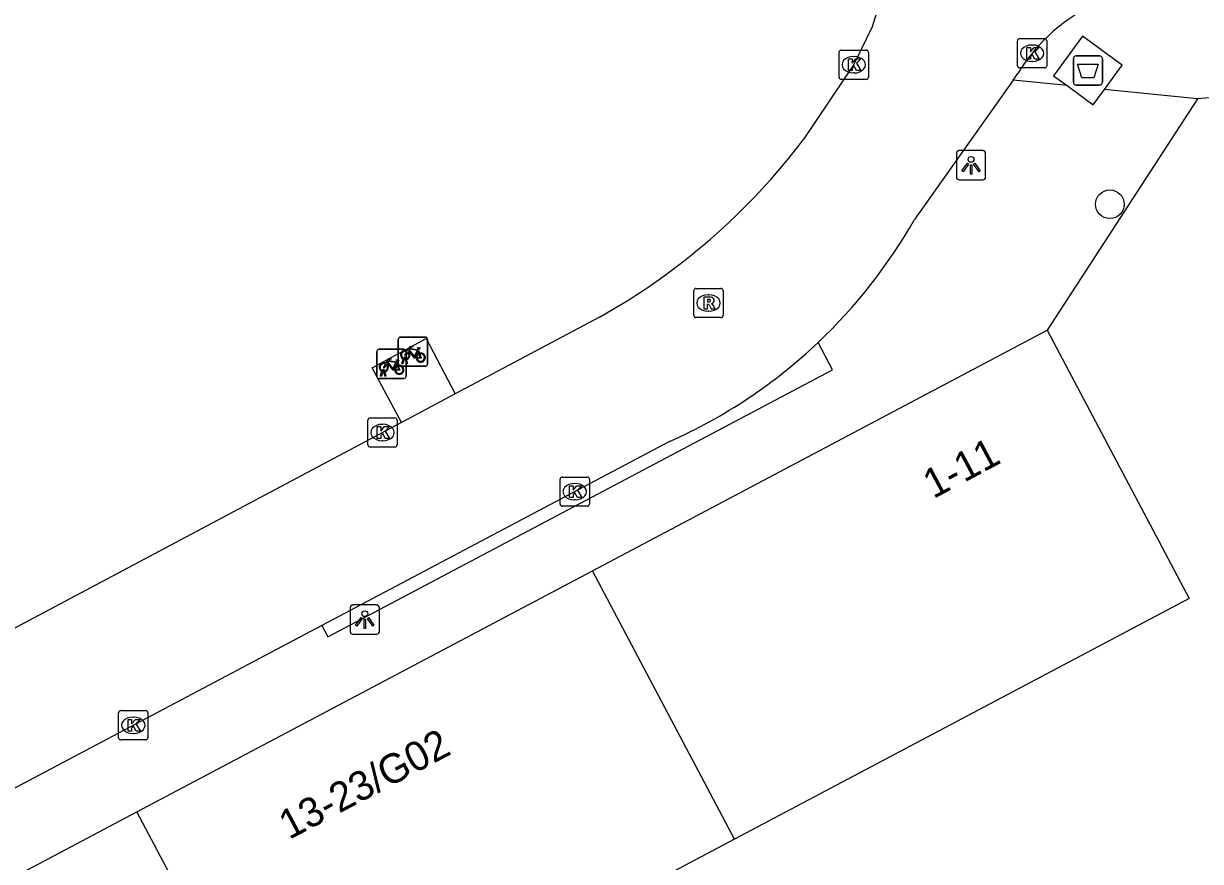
# Model space of a CAD drawing. Extents: x 159675 to 160530, y 382179 to 382901.
# Drawn here: x 160043.25 to 160083.44, y 382293.36 to 382321.97 of the extents above; entities that cross this region are included whole.
import ezdxf

# ---------------------------------------------------------------- set-up
doc = ezdxf.new("R2010")
doc.units = 0
for name, color, linetype in [('IMGEO_Afval_apart_plaats', 7, 'Continuous'), ('IMGEO_Boom', 7, 'Continuous'), ('IMGEO_Fietsenrek', 7, 'Continuous'), ('IMGEO_Groenvoorziening', 7, 'Continuous'), ('IMGEO_Kolk', 7, 'Continuous'), ('IMGEO_Lichtpunt', 7, 'Continuous'), ('IMGEO_Pand', 7, 'Continuous'), ('IMGEO_Pand_nummerreeks', 7, 'Continuous'), ('IMGEO_Rijbaan_lokaal_open', 7, 'Continuous'), ('IMGEO_Rioolput', 7, 'Continuous'), ('IMGEO_Voetpad_gesloten', 7, 'Continuous'), ('IMGEO_Voetpad_open', 7, 'Continuous')]:
    doc.layers.add(name, color=color, linetype=linetype)

msp = doc.modelspace()

# ---------------------------------------------------------------- linework, layer by layer
at = {"layer": 'IMGEO_Afval_apart_plaats'}
for p, q in [((160079.198, 382320.869), (160079.988, 382320.869)), ((160079.988, 382320.869), (160079.198, 382320.869)), ((160079.098, 382319.969), (160079.098, 382320.769)), ((160079.098, 382320.769), (160079.098, 382319.969)), ((160080.088, 382320.769), (160080.088, 382319.969)), ((160080.088, 382319.969), (160080.088, 382320.769)), ((160079.988, 382319.869), (160079.198, 382319.869)), ((160079.198, 382319.869), (160079.988, 382319.869))]:
    msp.add_line(p, q, dxfattribs=at)
msp.add_lwpolyline([(160079.241, 382320.583), (160079.945, 382320.583), (160079.796, 382320.113), (160079.39, 382320.113), (160079.241, 382320.583)], dxfattribs=at)
for centre, start, end in [((160079.198, 382320.769), 90, 180), ((160079.198, 382320.769), 90, 180), ((160079.988, 382320.769), 0, 90), ((160079.988, 382320.769), 360, 90), ((160079.198, 382319.969), 180, 270), ((160079.198, 382319.969), 180, 270), ((160079.988, 382319.969), 270, 0), ((160079.988, 382319.969), 270, 0)]:
    msp.add_arc(centre, 0.1, start, end, dxfattribs=at)
at = {"layer": 'IMGEO_Boom'}
msp.add_circle((160080.343, 382315.799), 0.489, dxfattribs=at)
at = {"layer": 'IMGEO_Fietsenrek'}
for p, q in [((160056.046, 382310.341), (160056.046, 382311.182)), ((160056.046, 382311.182), (160056.046, 382310.341)), ((160056.121, 382311.266), (160056.962, 382311.266)), ((160056.962, 382311.266), (160056.121, 382311.266)), ((160057.046, 382311.191), (160057.046, 382310.35)), ((160057.046, 382310.35), (160057.046, 382311.191)), ((160055.389, 382310.848), (160056.23, 382310.848)), ((160056.23, 382310.848), (160055.389, 382310.848)), ((160056.314, 382310.773), (160056.314, 382309.932)), ((160056.314, 382309.932), (160056.314, 382310.773)), ((160056.733, 382310.815), (160056.769, 382310.72)), ((160055.314, 382309.923), (160055.314, 382310.764)), ((160055.314, 382310.764), (160055.314, 382309.923)), ((160056.001, 382310.397), (160056.037, 382310.302)), ((160056.173, 382310.35), (160056.212, 382310.51)), ((160056.242, 382310.498), (160056.207, 382310.35)), ((160056.284, 382310.522), (160056.283, 382310.526)), ((160056.325, 382310.35), (160056.291, 382310.492)), ((160056.315, 382310.533), (160056.316, 382310.526)), ((160056.323, 382310.496), (160056.358, 382310.35)), ((160055.441, 382309.932), (160055.48, 382310.092)), ((160055.51, 382310.08), (160055.475, 382309.932)), ((160055.552, 382310.104), (160055.551, 382310.108)), ((160055.593, 382309.932), (160055.559, 382310.074)), ((160055.583, 382310.115), (160055.584, 382310.108)), ((160055.591, 382310.078), (160055.626, 382309.932)), ((160056.971, 382310.266), (160056.13, 382310.266)), ((160056.13, 382310.266), (160056.971, 382310.266)), ((160056.207, 382310.35), (160056.173, 382310.35)), ((160056.358, 382310.35), (160056.325, 382310.35)), ((160056.239, 382309.848), (160055.398, 382309.848)), ((160055.398, 382309.848), (160056.239, 382309.848)), ((160055.475, 382309.932), (160055.441, 382309.932)), ((160055.626, 382309.932), (160055.593, 382309.932))]:
    msp.add_line(p, q, dxfattribs=at)
for points in [[(160056.38, 382310.74), (160056.328, 382310.65), (160056.288, 382310.625), (160056.289, 382310.672), (160056.344, 382310.766)], [(160056.359, 382310.792), (160056.454, 382310.956), (160056.54, 382310.942), (160056.542, 382310.933), (160056.486, 382310.922), (160056.459, 382310.877), (160056.715, 382310.836)], [(160056.655, 382310.548), (160056.605, 382310.548), (160056.414, 382310.799), (160056.395, 382310.767)], [(160056.702, 382310.811), (160056.445, 382310.852), (160056.428, 382310.823), (160056.595, 382310.603), (160056.702, 382310.811)], [(160056.75, 382310.713), (160056.72, 382310.79), (160056.611, 382310.572), (160056.654, 382310.572)], [(160056.715, 382310.836), (160056.74, 382310.885), (160056.734, 382310.889), (160056.711, 382310.893), (160056.699, 382310.9), (160056.698, 382310.903), (160056.7, 382310.908), (160056.795, 382310.893), (160056.797, 382310.883), (160056.787, 382310.87), (160056.775, 382310.864), (160056.761, 382310.87), (160056.733, 382310.815)], [(160055.627, 382310.374), (160055.722, 382310.538), (160055.808, 382310.524), (160055.81, 382310.515), (160055.754, 382310.504), (160055.727, 382310.459), (160055.983, 382310.418)], [(160055.923, 382310.13), (160055.873, 382310.13), (160055.682, 382310.381), (160055.663, 382310.349)], [(160055.97, 382310.393), (160055.713, 382310.434), (160055.696, 382310.405), (160055.863, 382310.185), (160055.97, 382310.393)], [(160056.018, 382310.295), (160055.988, 382310.372), (160055.879, 382310.154), (160055.922, 382310.154)], [(160055.983, 382310.418), (160056.008, 382310.467), (160056.002, 382310.471), (160055.979, 382310.475), (160055.967, 382310.482), (160055.966, 382310.485), (160055.968, 382310.49), (160056.063, 382310.475), (160056.065, 382310.465), (160056.055, 382310.452), (160056.043, 382310.446), (160056.029, 382310.452), (160056.001, 382310.397)], [(160056.684, 382310.572), (160056.804, 382310.571), (160056.76, 382310.685)], [(160056.78, 382310.692), (160056.835, 382310.547), (160056.685, 382310.547)], [(160055.648, 382310.322), (160055.596, 382310.232), (160055.556, 382310.207), (160055.557, 382310.254), (160055.612, 382310.348)], [(160055.952, 382310.154), (160056.072, 382310.153), (160056.028, 382310.267)], [(160056.048, 382310.274), (160056.103, 382310.129), (160055.953, 382310.129)]]:
    msp.add_lwpolyline(points, dxfattribs=at)
for centre, radius, start, end in [((160056.124, 382311.188), 0.0779, 92.4484, 184.2845), ((160056.124, 382311.188), 0.0779, 92.4484, 184.2845), ((160056.968, 382311.188), 0.0779, 2.4484, 94.2845), ((160056.968, 382311.188), 0.0779, 2.4484, 94.2845), ((160055.392, 382310.77), 0.0779, 92.4484, 184.2845), ((160055.392, 382310.77), 0.0779, 92.4484, 184.2845), ((160056.286, 382310.651), 0.159, 62.6766, 242.1369), ((160056.286, 382310.651), 0.129, 63.3192, 238.903), ((160056.236, 382310.77), 0.0779, 2.4484, 94.2845), ((160056.236, 382310.77), 0.0779, 2.4484, 94.2845), ((160056.286, 382310.651), 0.159, 283.5766, 46.6042), ((160055.554, 382310.233), 0.159, 62.6766, 242.1369), ((160056.266, 382310.522), 0.0499, 12.8025, 158.6934), ((160056.286, 382310.651), 0.159, 253.9967, 271.7867), ((160056.266, 382310.522), 0.0174, 12.8025, 163.4502), ((160056.286, 382310.651), 0.129, 253.415, 269.0204), ((160056.286, 382310.651), 0.129, 283.6043, 43.4302), ((160056.813, 382310.567), 0.159, 113.3408, 178.3217), ((160056.813, 382310.567), 0.159, 187.0065, 105.7708), ((160056.813, 382310.567), 0.129, 113.923, 177.9556), ((160056.813, 382310.567), 0.129, 188.6715, 104.5883), ((160055.554, 382310.233), 0.129, 63.3192, 238.903), ((160055.534, 382310.104), 0.0499, 12.8025, 158.6934), ((160055.554, 382310.233), 0.159, 253.9967, 271.7867), ((160055.534, 382310.104), 0.0174, 12.8025, 163.4502), ((160055.554, 382310.233), 0.129, 253.415, 269.0204), ((160055.554, 382310.233), 0.129, 283.6043, 43.4302), ((160055.554, 382310.233), 0.159, 283.5766, 46.6042), ((160056.081, 382310.149), 0.159, 113.3408, 178.3217), ((160056.081, 382310.149), 0.159, 187.0065, 105.7708), ((160056.081, 382310.149), 0.129, 113.923, 177.9556), ((160056.081, 382310.149), 0.129, 188.6715, 104.5883), ((160056.124, 382310.344), 0.0779, 182.4484, 274.2845), ((160056.124, 382310.344), 0.0779, 182.4484, 274.2845), ((160056.968, 382310.344), 0.0779, 272.4484, 4.2845), ((160056.968, 382310.344), 0.0779, 272.4484, 4.2845), ((160055.392, 382309.926), 0.0779, 182.4484, 274.2845), ((160055.392, 382309.926), 0.0779, 182.4484, 274.2845), ((160056.236, 382309.926), 0.0779, 272.4484, 4.2845), ((160056.236, 382309.926), 0.0779, 272.4484, 4.2845)]:
    msp.add_arc(centre, radius, start, end, dxfattribs=at)
at = {"layer": 'IMGEO_Groenvoorziening'}
msp.add_lwpolyline([(160056.153, 382308.348), (160055.16, 382310.219), (160056.998, 382311.213), (160057.989, 382309.325)], dxfattribs=at)
at = {"layer": 'IMGEO_Kolk'}
for p, q in [((160077.188, 382320.533), (160077.188, 382321.385)), ((160077.263, 382321.459), (160078.115, 382321.459)), ((160077.676, 382321.239), (160077.701, 382321.239)), ((160078.189, 382321.385), (160078.189, 382320.533)), ((160071.1, 382320.139), (160071.1, 382320.991)), ((160071.175, 382321.065), (160072.027, 382321.065)), ((160071.588, 382320.845), (160071.613, 382320.845)), ((160072.101, 382320.991), (160072.101, 382320.139)), ((160078.115, 382320.459), (160077.263, 382320.459)), ((160077.699, 382320.679), (160077.674, 382320.679)), ((160072.027, 382320.065), (160071.175, 382320.065)), ((160071.611, 382320.285), (160071.586, 382320.285)), ((160055.008, 382307.579), (160055.008, 382308.431)), ((160055.083, 382308.505), (160055.935, 382308.505)), ((160056.009, 382308.431), (160056.009, 382307.579)), ((160055.496, 382308.285), (160055.521, 382308.285)), ((160055.519, 382307.725), (160055.494, 382307.725)), ((160055.935, 382307.505), (160055.083, 382307.505)), ((160061.572, 382305.56), (160061.572, 382306.412)), ((160061.647, 382306.486), (160062.499, 382306.486)), ((160062.573, 382306.412), (160062.573, 382305.56)), ((160062.06, 382306.266), (160062.085, 382306.266)), ((160062.083, 382305.706), (160062.058, 382305.706)), ((160062.499, 382305.486), (160061.647, 382305.486)), ((160046.5, 382297.581), (160046.5, 382298.433)), ((160046.575, 382298.507), (160047.427, 382298.507)), ((160047.501, 382298.433), (160047.501, 382297.581)), ((160046.988, 382298.287), (160047.013, 382298.287)), ((160047.427, 382297.507), (160046.575, 382297.507)), ((160047.011, 382297.727), (160046.986, 382297.727))]:
    msp.add_line(p, q, dxfattribs=at)
for points in [[(160077.188, 382320.533), (160077.188, 382321.385)], [(160077.263, 382321.459), (160078.115, 382321.459)], [(160078.189, 382321.385), (160078.189, 382320.533)], [(160071.1, 382320.139), (160071.1, 382320.991)], [(160071.175, 382321.065), (160072.027, 382321.065)], [(160072.101, 382320.991), (160072.101, 382320.139)], [(160077.509, 382321.159), (160077.632, 382321.159), (160077.632, 382321.008), (160077.762, 382321.159), (160077.926, 382321.159), (160077.78, 382321.008), (160077.933, 382320.759), (160077.781, 382320.759), (160077.696, 382320.923), (160077.632, 382320.856), (160077.632, 382320.759), (160077.509, 382320.759), (160077.509, 382321.159)], [(160071.421, 382320.765), (160071.544, 382320.765), (160071.544, 382320.614), (160071.674, 382320.765), (160071.838, 382320.765), (160071.692, 382320.614), (160071.845, 382320.365), (160071.693, 382320.365), (160071.608, 382320.529), (160071.544, 382320.462), (160071.544, 382320.365), (160071.421, 382320.365), (160071.421, 382320.765)], [(160078.115, 382320.459), (160077.263, 382320.459)], [(160072.027, 382320.065), (160071.175, 382320.065)], [(160055.008, 382307.579), (160055.008, 382308.431)], [(160055.083, 382308.505), (160055.935, 382308.505)], [(160056.009, 382308.431), (160056.009, 382307.579)], [(160055.329, 382308.205), (160055.452, 382308.205), (160055.452, 382308.054), (160055.582, 382308.205), (160055.746, 382308.205), (160055.6, 382308.054), (160055.753, 382307.805), (160055.601, 382307.805), (160055.516, 382307.969), (160055.452, 382307.902), (160055.452, 382307.805), (160055.329, 382307.805), (160055.329, 382308.205)], [(160055.935, 382307.505), (160055.083, 382307.505)], [(160061.572, 382305.56), (160061.572, 382306.412)], [(160061.647, 382306.486), (160062.499, 382306.486)], [(160062.573, 382306.412), (160062.573, 382305.56)], [(160061.893, 382306.186), (160062.016, 382306.186), (160062.016, 382306.035), (160062.146, 382306.186), (160062.31, 382306.186), (160062.164, 382306.035), (160062.317, 382305.786), (160062.165, 382305.786), (160062.08, 382305.95), (160062.016, 382305.883), (160062.016, 382305.786), (160061.893, 382305.786), (160061.893, 382306.186)], [(160062.499, 382305.486), (160061.647, 382305.486)], [(160046.5, 382297.581), (160046.5, 382298.433)], [(160046.575, 382298.507), (160047.427, 382298.507)], [(160047.501, 382298.433), (160047.501, 382297.581)], [(160046.821, 382298.207), (160046.944, 382298.207), (160046.944, 382298.056), (160047.074, 382298.207), (160047.238, 382298.207), (160047.092, 382298.056), (160047.245, 382297.807), (160047.093, 382297.807), (160047.008, 382297.971), (160046.944, 382297.904), (160046.944, 382297.807), (160046.821, 382297.807), (160046.821, 382298.207)], [(160047.427, 382297.507), (160046.575, 382297.507)]]:
    msp.add_lwpolyline(points, dxfattribs=at)
for centre, start, end in [((160077.265, 382321.383), 91.552, 178.448), ((160077.265, 382321.383), 91.552, 178.448), ((160078.113, 382321.383), 1.552, 88.448), ((160078.113, 382321.383), 1.552, 88.448), ((160071.177, 382320.989), 91.552, 178.448), ((160071.177, 382320.989), 91.552, 178.448), ((160072.025, 382320.989), 1.552, 88.448), ((160072.025, 382320.989), 1.552, 88.448), ((160077.265, 382320.535), 181.552, 268.448), ((160077.265, 382320.535), 181.552, 268.448), ((160078.113, 382320.535), 271.552, 358.448), ((160078.113, 382320.535), 271.552, 358.448), ((160071.177, 382320.141), 181.552, 268.448), ((160071.177, 382320.141), 181.552, 268.448), ((160072.025, 382320.141), 271.552, 358.448), ((160072.025, 382320.141), 271.552, 358.448), ((160055.085, 382308.429), 91.552, 178.448), ((160055.085, 382308.429), 91.552, 178.448), ((160055.933, 382308.429), 1.552, 88.448), ((160055.933, 382308.429), 1.552, 88.448), ((160055.085, 382307.581), 181.552, 268.448), ((160055.085, 382307.581), 181.552, 268.448), ((160055.933, 382307.581), 271.552, 358.448), ((160055.933, 382307.581), 271.552, 358.448), ((160061.649, 382306.41), 91.552, 178.448), ((160061.649, 382306.41), 91.552, 178.448), ((160062.497, 382306.41), 1.552, 88.448), ((160062.497, 382306.41), 1.552, 88.448), ((160061.649, 382305.562), 181.552, 268.448), ((160061.649, 382305.562), 181.552, 268.448), ((160062.497, 382305.562), 271.552, 358.448), ((160062.497, 382305.562), 271.552, 358.448), ((160046.577, 382298.431), 91.552, 178.448), ((160046.577, 382298.431), 91.552, 178.448), ((160047.425, 382298.431), 1.552, 88.448), ((160047.425, 382298.431), 1.552, 88.448), ((160046.577, 382297.583), 181.552, 268.448), ((160046.577, 382297.583), 181.552, 268.448), ((160047.425, 382297.583), 271.552, 358.448), ((160047.425, 382297.583), 271.552, 358.448)]:
    msp.add_arc(centre, 0.0765, start, end, dxfattribs=at)
for centre, major_axis, ratio, start_param, end_param in [((160077.675, 382320.959), (-0.387, 0.002), 0.722429, 4.712389, 7.853982), ((160077.7, 382320.959), (-0.39, 0.002), 0.717154, 1.570796, 4.712389), ((160071.587, 382320.565), (-0.387, 0.002), 0.722429, 4.712389, 7.853982), ((160071.612, 382320.565), (-0.39, 0.002), 0.717154, 1.570796, 4.712389), ((160055.495, 382308.005), (-0.387, 0.002), 0.722429, 4.712389, 7.853982), ((160055.52, 382308.005), (-0.39, 0.002), 0.717154, 1.570796, 4.712389), ((160062.059, 382305.986), (-0.387, 0.002), 0.722429, 4.712389, 7.853982), ((160062.084, 382305.986), (-0.39, 0.002), 0.717154, 1.570796, 4.712389), ((160046.987, 382298.007), (-0.387, 0.002), 0.722429, 4.712389, 7.853982), ((160047.012, 382298.007), (-0.39, 0.002), 0.717154, 1.570796, 4.712389)]:
    msp.add_ellipse(centre, major_axis=major_axis, ratio=ratio, start_param=start_param, end_param=end_param, dxfattribs=at)
at = {"layer": 'IMGEO_Lichtpunt'}
for p, q in [((160076.007, 382317.631), (160075.199, 382317.631)), ((160076.007, 382317.631), (160075.199, 382317.631)), ((160075.105, 382317.536), (160075.105, 382316.729)), ((160075.105, 382317.536), (160075.105, 382316.729)), ((160076.101, 382316.729), (160076.101, 382317.536)), ((160076.101, 382316.729), (160076.101, 382317.536)), ((160075.199, 382316.635), (160076.007, 382316.635)), ((160075.199, 382316.635), (160076.007, 382316.635)), ((160054.406, 382302.02), (160054.406, 382301.213)), ((160054.406, 382302.02), (160054.406, 382301.213)), ((160055.308, 382302.115), (160054.5, 382302.115)), ((160055.308, 382302.115), (160054.5, 382302.115)), ((160055.402, 382301.213), (160055.402, 382302.02)), ((160055.402, 382301.213), (160055.402, 382302.02)), ((160054.5, 382301.119), (160055.308, 382301.119)), ((160054.5, 382301.119), (160055.308, 382301.119))]:
    msp.add_line(p, q, dxfattribs=at)
for points in [[(160075.479, 382317.2), (160075.518, 382317.172), (160075.33, 382316.91), (160075.292, 382316.937), (160075.479, 382317.2)], [(160075.691, 382317.172), (160075.729, 382317.199), (160075.916, 382316.937), (160075.877, 382316.909), (160075.691, 382317.172)], [(160075.581, 382317.152), (160075.628, 382317.152), (160075.628, 382316.83), (160075.581, 382316.83), (160075.581, 382317.152)], [(160054.78, 382301.684), (160054.819, 382301.656), (160054.631, 382301.394), (160054.593, 382301.421), (160054.78, 382301.684)], [(160054.882, 382301.636), (160054.929, 382301.636), (160054.929, 382301.314), (160054.882, 382301.314), (160054.882, 382301.636)], [(160054.992, 382301.656), (160055.03, 382301.683), (160055.217, 382301.421), (160055.178, 382301.393), (160054.992, 382301.656)]]:
    msp.add_lwpolyline(points, dxfattribs=at)
for centre in [(160075.604, 382317.334), (160054.905, 382301.818)]:
    msp.add_circle(centre, 0.0994, dxfattribs=at)
for centre, start, end in [((160075.199, 382317.536), 90, 180), ((160075.199, 382317.536), 90, 180), ((160076.007, 382317.536), 0, 90), ((160076.007, 382317.536), 0, 90), ((160075.199, 382316.729), 180, 270), ((160075.199, 382316.729), 180, 270), ((160076.007, 382316.729), 270, 0), ((160076.007, 382316.729), 270, 360), ((160054.5, 382302.02), 90, 180), ((160054.5, 382302.02), 90, 180), ((160055.308, 382302.02), 0, 90), ((160055.308, 382302.02), 0, 90), ((160054.5, 382301.213), 180, 270), ((160054.5, 382301.213), 180, 270), ((160055.308, 382301.213), 270, 0), ((160055.308, 382301.213), 270, 360)]:
    msp.add_arc(centre, 0.0946, start, end, dxfattribs=at)
at = {"layer": 'IMGEO_Pand'}
for points in [[(160062.679, 382303.28), (160078.204, 382311.499)], [(160078.204, 382311.499), (160083.057, 382302.331), (160067.532, 382294.112)], [(160047.124, 382295.046), (160062.679, 382303.28)], [(160067.532, 382294.112), (160062.679, 382303.28)], [(160031.569, 382286.811), (160047.124, 382295.046)], [(160051.977, 382285.878), (160047.124, 382295.046)], [(160067.532, 382294.112), (160051.977, 382285.878)]]:
    msp.add_lwpolyline(points, dxfattribs=at)
at = {"layer": 'IMGEO_Rijbaan_lokaal_open'}
for points in [[(160072.647, 382323.232), (160072.224, 382321.861), (160071.602, 382320.568), (160069.876, 382317.999)], [(160077.045, 382320.041), (160073.671, 382315.279)], [(160077.045, 382320.041), (160077.204, 382320.266)], [(160062.919, 382311.947), (160057.989, 382309.325)], [(160057.989, 382309.325), (160056.153, 382308.348)], [(160056.153, 382308.348), (160037.122, 382298.226)], [(160065.313, 382307.7), (160053.435, 382301.412)], [(160053.435, 382301.412), (160038.601, 382293.559)]]:
    msp.add_lwpolyline(points, dxfattribs=at)
for centre, radius, start, end in [((160082.399, 382317.141), 6.062, 117.2616, 148.9706), ((160051.898, 382331.641), 22.568, 299.2325, 322.8085), ((160057.98, 382324.176), 18.038, 313.4498, 330.4459), ((160057.989, 382324.182), 18.036, 293.9587, 313.4163)]:
    msp.add_arc(centre, radius, start, end, dxfattribs=at)
at = {"layer": 'IMGEO_Rioolput'}
for p, q in [((160066.14, 382312.002), (160066.14, 382312.854)), ((160066.215, 382312.928), (160067.067, 382312.928)), ((160067.141, 382312.854), (160067.141, 382312.002)), ((160066.628, 382312.708), (160066.653, 382312.708)), ((160066.651, 382312.148), (160066.626, 382312.148)), ((160067.067, 382311.928), (160066.215, 382311.928))]:
    msp.add_line(p, q, dxfattribs=at)
for points in [[(160066.14, 382312.002), (160066.14, 382312.854)], [(160066.215, 382312.928), (160067.067, 382312.928)], [(160067.141, 382312.854), (160067.141, 382312.002)], [(160066.729, 382312.626), (160066.477, 382312.628), (160066.477, 382312.228)], [(160066.477, 382312.228), (160066.601, 382312.228), (160066.601, 382312.39), (160066.612, 382312.39)], [(160066.655, 382312.547), (160066.601, 382312.547), (160066.601, 382312.466)], [(160066.601, 382312.466), (160066.653, 382312.466)], [(160066.659, 382312.361), (160066.73, 382312.228), (160066.87, 382312.228), (160066.805, 382312.354)], [(160067.067, 382311.928), (160066.215, 382311.928)]]:
    msp.add_lwpolyline(points, dxfattribs=at)
for centre, radius, start, end in [((160066.217, 382312.852), 0.0765, 91.552, 178.448), ((160066.217, 382312.852), 0.0765, 91.552, 178.448), ((160067.065, 382312.852), 0.0765, 1.552, 88.448), ((160067.065, 382312.852), 0.0765, 1.552, 88.448), ((160066.611, 382312.337), 0.0533, 26.0293, 88.6989), ((160066.637, 382312.655), 0.19, 274.7715, 282.9687), ((160066.661, 382312.451), 0.0964, 77.0061, 93.1865), ((160066.675, 382312.508), 0.0378, 276.6634, 79.6772), ((160066.728, 382312.516), 0.109, 350.3612, 89.416), ((160066.726, 382312.516), 0.112, 277.5842, 350.9817), ((160066.71, 382312.301), 0.108, 29.5134, 73.7905), ((160066.217, 382312.004), 0.0765, 181.552, 268.448), ((160066.217, 382312.004), 0.0765, 181.552, 268.448), ((160067.065, 382312.004), 0.0765, 271.552, 358.448), ((160067.065, 382312.004), 0.0765, 271.552, 358.448)]:
    msp.add_arc(centre, radius, start, end, dxfattribs=at)
for centre, major_axis, ratio, start_param, end_param in [((160066.627, 382312.428), (-0.387, 0.002), 0.722429, 4.712389, 7.853982), ((160066.652, 382312.428), (-0.39, 0.002), 0.717154, 1.570796, 4.712389)]:
    msp.add_ellipse(centre, major_axis=major_axis, ratio=ratio, start_param=start_param, end_param=end_param, dxfattribs=at)
at = {"layer": 'IMGEO_Voetpad_gesloten'}
for points in [[(160080.16, 382319.722), (160080.762, 382320.55), (160079.406, 382321.537), (160078.424, 382320.188), (160078.885, 382319.853)], [(160078.885, 382319.853), (160079.78, 382319.201), (160080.16, 382319.722)]]:
    msp.add_lwpolyline(points, dxfattribs=at)
at = {"layer": 'IMGEO_Voetpad_open'}
for points in [[(160078.885, 382319.853), (160077.045, 382320.041)], [(160083.339, 382319.397), (160080.16, 382319.722)], [(160086.028, 382319.631), (160083.339, 382319.397)], [(160083.339, 382319.397), (160078.204, 382311.499)], [(160053.435, 382301.412), (160053.641, 382301.024), (160070.878, 382310.15), (160070.385, 382311.081)]]:
    msp.add_lwpolyline(points, dxfattribs=at)

# ---------------------------------------------------------------- texts
at = {"layer": 'IMGEO_Pand_nummerreeks'}
for s, rotation, p in [('1-11', 28.1313, (160074.318, 382305.727)), ('13-23/G02', 27.8957, (160052.322, 382294.086))]:
    msp.add_text(s, height=1, rotation=rotation, dxfattribs=at).set_placement(p)

doc.saveas('drawing.dxf')
